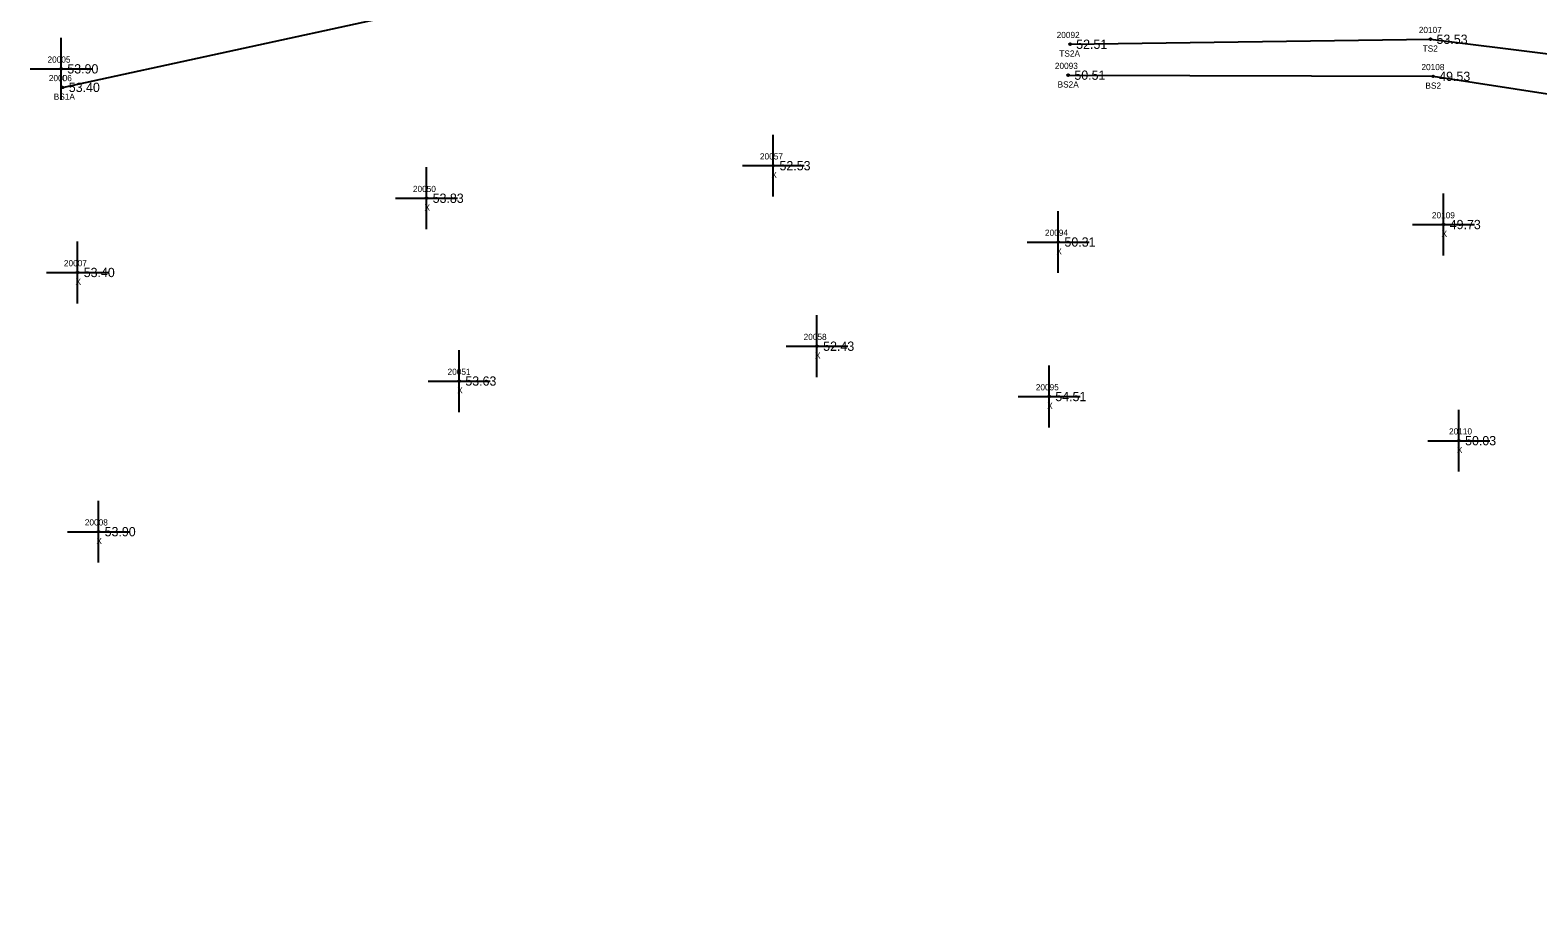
# Model space of a CAD drawing. Extents: x 2420351 to 2422725, y 845330 to 846558.
# Drawn here: x 2420386.4 to 2420630.1, y 845524.4 to 845665.9 of the extents above; entities that cross this region are included whole.
import ezdxf

# ---------------------------------------------------------------- set-up
doc = ezdxf.new("R2010")
doc.units = 0
for name, color, linetype in [('RD_DTM_BkLn2', 7, 'Continuous'), ('RD_DTM_BkLn_txCode', 7, 'Continuous'), ('RD_EX_Misc', 7, 'Continuous'), ('RD_EX_Misc_txCode', 7, 'Continuous'), ('RD_EX_TX_Misc_ELEV', 7, 'Continuous'), ('RD_SMD_Locator', 7, 'Continuous')]:
    doc.layers.add(name, color=color, linetype=linetype)

msp = doc.modelspace()

# ---------------------------------------------------------------- linework, layer by layer
at = {"layer": 'RD_DTM_BkLn2'}
for points in [[(2420391.68, 845656.64), (2420445.21, 845668.26), (2420499.47, 845673.15), (2420555.79, 845685.67), (2420611.25, 845685.1), (2420638.03, 845688.28), (2420664.95, 845679.28), (2420684.17, 845674.37), (2420751.52, 845659.06), (2420788.44, 845663), (2420892.57, 845636.64), (2420995.04, 845591.46), (2421010.85, 845555.52)], [(2420554.48, 845663.6), (2420612.71, 845664.41), (2420685.79, 845655.34), (2420750.14, 845647.33), (2420785.66, 845648.26), (2420885.87, 845623.22), (2421008.49, 845539.14)], [(2420554.18, 845658.61), (2420613.14, 845658.42), (2420684.62, 845647.43), (2420749.31, 845640.38), (2420783.25, 845635.49), (2420872.47, 845596.38), (2421005.56, 845524.43)]]:
    msp.add_lwpolyline(points, dxfattribs=at)
at = {"layer": 'RD_EX_Misc'}
for p, q in [((2420391.44, 845654.63), (2420391.44, 845664.63)), ((2420386.44, 845659.63), (2420396.44, 845659.63)), ((2420506.53, 845638.99), (2420506.53, 845648.99)), ((2420450.48, 845633.73), (2420450.48, 845643.73)), ((2420501.53, 845643.99), (2420511.53, 845643.99)), ((2420445.48, 845638.73), (2420455.48, 845638.73)), ((2420614.84, 845629.48), (2420614.84, 845639.48)), ((2420552.58, 845626.66), (2420552.58, 845636.66)), ((2420609.84, 845634.48), (2420619.84, 845634.48)), ((2420394.09, 845621.74), (2420394.09, 845631.74)), ((2420547.58, 845631.66), (2420557.58, 845631.66)), ((2420389.09, 845626.74), (2420399.09, 845626.74)), ((2420513.59, 845609.83), (2420513.59, 845619.83)), ((2420455.76, 845604.2), (2420455.76, 845614.2)), ((2420508.59, 845614.83), (2420518.59, 845614.83)), ((2420551.1, 845601.7), (2420551.1, 845611.7)), ((2420450.76, 845609.2), (2420460.76, 845609.2)), ((2420546.1, 845606.7), (2420556.1, 845606.7)), ((2420617.32, 845594.57), (2420617.32, 845604.57)), ((2420612.32, 845599.57), (2420622.32, 845599.57)), ((2420397.47, 845579.87), (2420397.47, 845589.87)), ((2420392.47, 845584.87), (2420402.47, 845584.87))]:
    msp.add_line(p, q, dxfattribs=at)
at = {"layer": 'RD_SMD_Locator'}
for centre in [(2420612.71, 845664.41), (2420554.48, 845663.6), (2420391.44, 845659.63), (2420554.18, 845658.61), (2420613.14, 845658.42), (2420391.68, 845656.64), (2420506.53, 845643.99), (2420450.48, 845638.73), (2420614.84, 845634.48), (2420552.58, 845631.66), (2420394.09, 845626.74), (2420513.59, 845614.83), (2420455.76, 845609.2), (2420551.1, 845606.7), (2420617.32, 845599.57), (2420397.47, 845584.87)]:
    msp.add_circle(centre, 0.15, dxfattribs=at)

# ---------------------------------------------------------------- texts
at = {"layer": 'RD_DTM_BkLn_txCode'}
for s, p in [('20092', (2420552.32, 845664.6)), ('20107', (2420610.84, 845665.41)), ('TS2A', (2420552.75, 845661.6)), ('TS2', (2420611.47, 845662.41)), ('20093', (2420552.03, 845659.61)), ('20108', (2420611.27, 845659.42)), ('20006', (2420389.46, 845657.64)), ('BS2A', (2420552.47, 845656.61)), ('BS2', (2420611.91, 845656.42)), ('BS1A', (2420390.25, 845654.64))]:
    msp.add_text(s, height=1, dxfattribs=at).set_placement(p)
at = {"layer": 'RD_EX_Misc_txCode'}
for s, p in [('20005', (2420389.24, 845660.63)), ('X', (2420391.12, 845657.63)), ('20057', (2420504.37, 845644.99)), ('X', (2420506.22, 845641.99)), ('20050', (2420448.29, 845639.73)), ('X', (2420450.17, 845636.73)), ('20109', (2420612.96, 845635.48)), ('20094', (2420550.43, 845632.66)), ('X', (2420614.52, 845632.48)), ('X', (2420552.27, 845629.66)), ('20007', (2420391.89, 845627.74)), ('X', (2420393.77, 845624.74)), ('20058', (2420511.43, 845615.83)), ('X', (2420513.27, 845612.83)), ('20051', (2420453.89, 845610.2)), ('X', (2420455.45, 845607.2)), ('20095', (2420548.95, 845607.7)), ('X', (2420550.79, 845604.7)), ('20110', (2420615.73, 845600.57)), ('X', (2420617, 845597.57)), ('20008', (2420395.27, 845585.87)), ('X', (2420397.15, 845582.87))]:
    msp.add_text(s, height=1, dxfattribs=at).set_placement(p)
at = {"layer": 'RD_EX_TX_Misc_ELEV'}
for s, p in [('52.51', (2420555.48, 845662.85)), ('53.53', (2420613.71, 845663.66)), ('53.90', (2420392.44, 845658.88)), ('50.51', (2420555.18, 845657.86)), ('53.40', (2420392.68, 845655.89)), ('49.53', (2420614.14, 845657.67)), ('52.53', (2420507.53, 845643.24)), ('53.83', (2420451.48, 845637.98)), ('49.73', (2420615.84, 845633.73)), ('50.31', (2420553.58, 845630.91)), ('53.40', (2420395.09, 845625.99)), ('52.43', (2420514.59, 845614.08)), ('53.63', (2420456.76, 845608.45)), ('54.51', (2420552.1, 845605.95)), ('50.03', (2420618.32, 845598.82)), ('53.90', (2420398.47, 845584.12))]:
    msp.add_text(s, height=1.5, dxfattribs=at).set_placement(p)

doc.saveas('drawing.dxf')
